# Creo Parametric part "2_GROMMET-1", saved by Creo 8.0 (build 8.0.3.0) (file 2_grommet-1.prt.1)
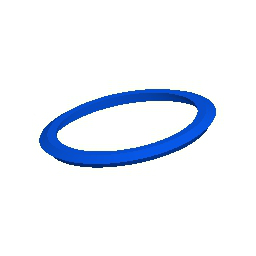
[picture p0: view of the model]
Units: millimeter Newton Second (mmNs); MM, TONNE, SECS

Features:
  1. datum plane "DTM1"
  2. protrusion
  3. datum plane "DTM2"
  4. protrusion
  5. cut

Layers: 0_ALL_AXIS, 0_ALL_CSYS, 0_ALL_CURVES, 0_ALL_PLANES, 0_ALL_POINTS, 0_ALL_SURFS, GROMMET-1

Surfaces: 10 cone, 3 cylinder, 3 plane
